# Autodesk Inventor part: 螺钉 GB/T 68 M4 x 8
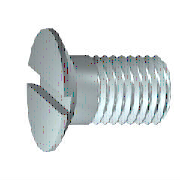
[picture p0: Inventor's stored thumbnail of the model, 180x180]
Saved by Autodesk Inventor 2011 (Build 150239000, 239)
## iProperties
Created: 2010-02
Part Number: 螺钉 GB/T 68 M4 x 8
Material: 低炭钢
Description: 开槽沉头螺钉
Document SubType Name: Modeling
Standard: GB/T 68-2000
Designer: Administrator
Standard Revision: 2000
Standards Organization: GB
Language: zh-CN
Size Designation: M4x8
Categories: <MemberInstance><Categories><Category DisplayName="紧固件" InternalName="e4da775c-781d-43d5-af7c-5136215cf5a6" Mnemonic="FSTN"><Category DisplayName="螺栓" InternalN
Density: 1 g/cm^3
IsCustomPart: 1
Author: Administrator
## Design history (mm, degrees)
body "Solid1"
sketch "Sketch1"
  geometry: L1 (2.928, 1.773)-(0.5, 4.2); L2 (0.5, 4.2)-(0, 4.2); L3 (0, 4.2)-(0, 0); L4 (0, 0)-(8, 0); L5 (8, 2)-(4.1, 2); L6 (4.1, 2)-(3.671, 1.773); L7 (3.671, 1.773)-(2.928, 1.773); L8 (4.1, 2)-(2.7, 2); L9 (8, 0)-(8, 2); L10 (-1.6, 0)-(9.6, 0) reference; L11 (0, 5.04)-(0, -0.84) reference
  constraints: 18 end point, 4 parallel, 2 collinear, 2 perpendicular, 1 horizontal, 1 point on line
  dimensions: "d0" = 8 distance of L3.end L4.end (= NLG); "d1" = 45 deg angle of L1 L4 (= 0.5 x SEWI); "d2" = 0.42941 horizontal distance of L5.end L6.end (= GAL); "d3" = 3.9 distance from line of L9 L5.end (= GEL); "d4" = 2.7 distance from line of L8.end L3 (= KOH); "d5" = 3.545 diameter of L6.end L4 (= BDM); "d6" = 4 diameter of L5 L4 (= GD); "d7" = 8.4 diameter of L2 L4 (= KOD)
workplane "Work Plane1"
fillet "Fillet" dims "d41" = 1 (= RR)
revolve "Body" stored, may be unused: angle "d19" = 90 deg
sketch "Sketch2"
  geometry: L1 (4.2, -0.6)-(-4.2, -0.6); L2 (-4.2, -0.6)-(-4.2, 0.6); L3 (-4.2, 0.6)-(4.2, 0.6); L4 (4.2, 0.6)-(4.2, -0.6); L5 (0, 0.6)-(0, -0.6); L6 (-4.2, 0)-(4.2, 0); L7 (0, 4.2)-(0, 0) reference; 2 further points
  constraints: 12 end point, 5 midpoint, 2 parallel, 1 collinear, 1 horizontal, 1 perpendicular
  dimensions: "d15" = 1.2 distance of L3.end L1.start (= SBR); "d16" = 8.4 distance of L1.start L1.end (= KOD)
extrude "Slot" cut sketch "Sketch2" distance "d8" = 1.3 (= STI); taper "d9" = 0 deg
feature "Thread" dims "d10" = 3.9 (= GEL), "d11" = 0
chamfer "Chamfer1" distance "d12" = 0.42941 (= -0.5 x SPD + 0.5 x GD); stored, may be unused: second distance "d13" = 0.21471 (= 0.5 x GAL), angle "d35" = 45 deg
other parameters: "NLG" = 8 [user parameter; used in 1 equation term], "GAL" = 0.42941 (= 0.61345 x PTC) [user parameter; used in 2 equation terms], "GEL" = 3.9 [user parameter; used in 2 equation terms], "KOH" = 2.7 [user parameter; used in 1 equation term], "KOD" = 8.4 [user parameter; used in 2 equation terms], "SEWI" = 90 deg [user parameter; used in 1 equation term], "BDM" = 3.545 [user parameter; used in 1 equation term], "GD" = 4 (= NND) [user parameter; used in 2 equation terms], "SBR" = 1.2 [user parameter; used in 1 equation term], "STI" = 1.3 [user parameter; used in 1 equation term], "d17" = 0, "SPD" = 3.14117 (= NND - 1.2269 x PTC) [user parameter; used in 1 equation term], "d39" = 0, "d40" = 0, "RR" = 1 [user parameter; used in 1 equation term], "GUL" = 0.42941 (= 0.61345 x PTC) [user parameter], "PTC" = 0.7 [user parameter; used in 5 equation terms], "EPV" = 4.7 [user parameter], "THREADDIA" = 4 [user parameter; used in 1 equation term], "TOA" = 30 deg [user parameter], "FAWI" = 90 deg [user parameter], "TPU" = 14.28571 (computed from PTC) [user parameter], "NND" = 4 [user parameter; used in 2 equation terms], "GD1" = 3.14117 (= THREADDIA - 1.2269 x PTC) [user parameter]
